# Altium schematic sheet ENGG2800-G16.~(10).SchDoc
size A3
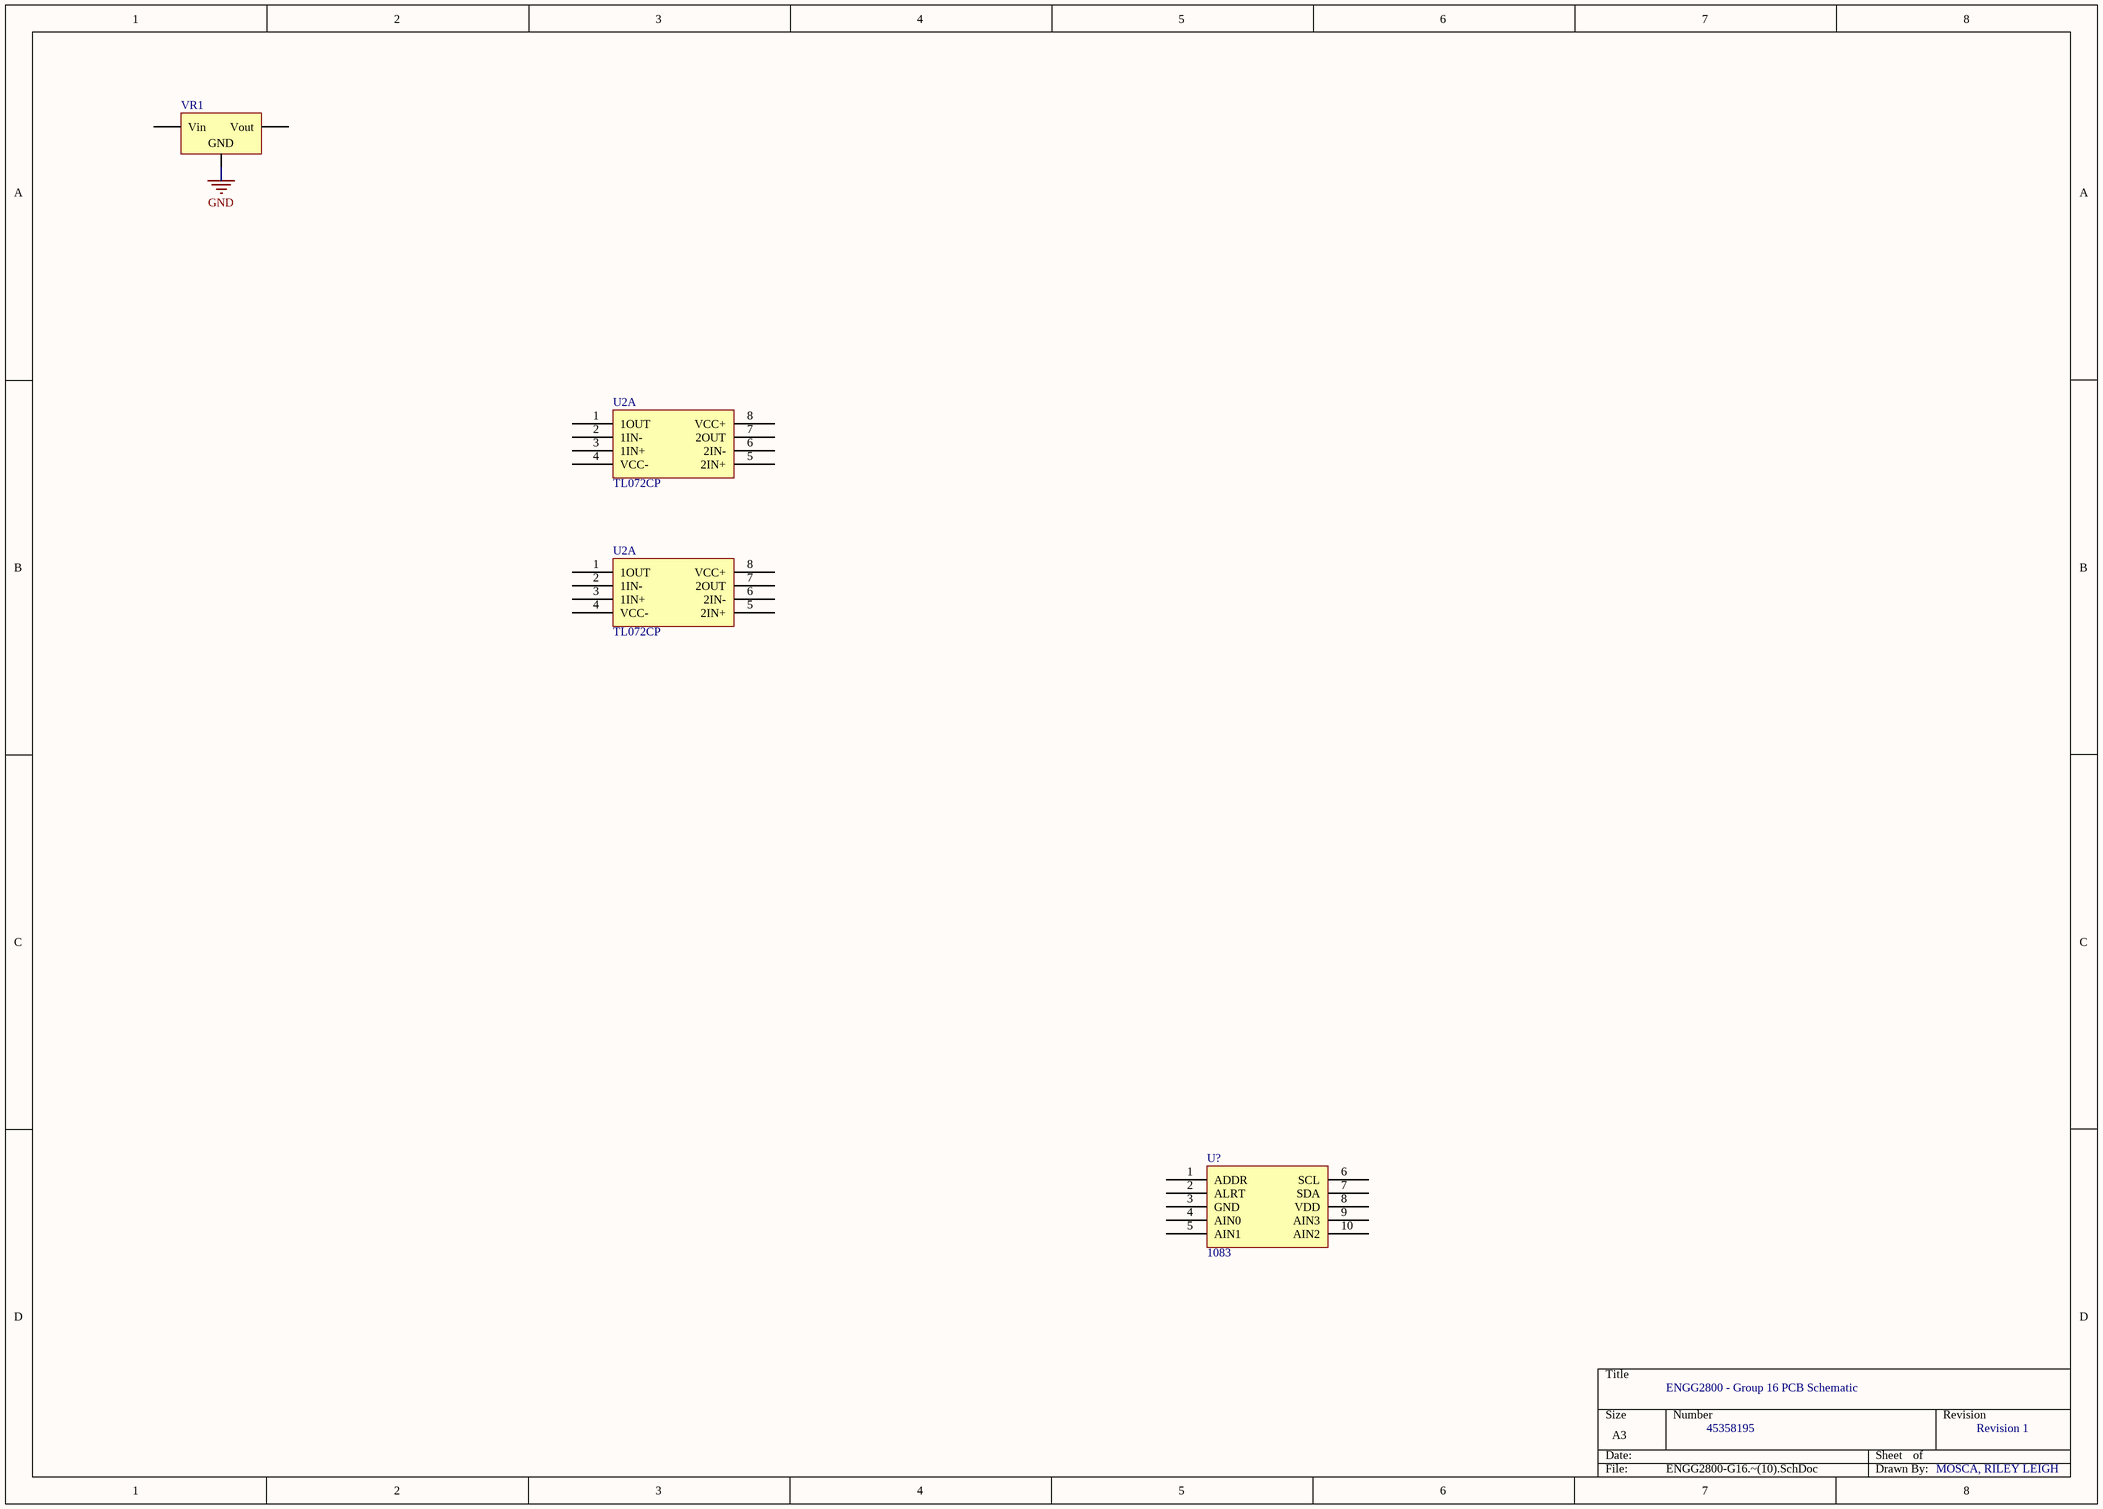
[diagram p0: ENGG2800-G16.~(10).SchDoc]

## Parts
(Parts that share a designator on the sheet are numbered #1, #2 ... from top to bottom, then left to right.)
U2#1  TL072CP  (part A of 4)
U2#2  TL072CP  (part A of 4)
U?  1083
VR1  Volt Reg  [D2PAK_N]  (value not drawn)

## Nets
GND: VR1.2(GND)

Not connected (* = marked no-connect by the designer): U2#1 1(1OUT) 2(1IN-) 3(1IN+) 4(VCC-) 5(2IN+) 6(2IN-) 7(2OUT) 8(VCC+); U2#2 1(1OUT) 2(1IN-) 3(1IN+) 4(VCC-) 5(2IN+) 6(2IN-) 7(2OUT) 8(VCC+); U? 1(ADDR) 2(ALRT) 3(GND) 4(AIN0) 5(AIN1) 6(SCL) 7(SDA) 8(VDD) 9(AIN3) 10(AIN2); VR1 1(Vin) 3(Vout)

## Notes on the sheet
- ENGG2800 - Group 16 PCB Schematic
- 45358195
- Revision 1
- MOSCA, RILEY LEIGH

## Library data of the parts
U2#1 U2#2 = TL072CP: IC, OP AMP, DUAL JFET, DIP8; Bandwidth:3MHz; No. of Amplifiers:2; Slew Rate:13V/ s; Supply Voltage Range:7V to 36V; Amplifier Case Style:DIP; No. of Pins:8; Operating Temperature Min:0 C; Operating Temperature Max:70 C; ;RoHS Compliant: Yes; Manufacturer: Texas Instruments; Bandwidth: 3MHz; Number of Channels: 2; Voltage Gain: 106.02dB; Nominal Supply Current: 5mA; Max Supply Voltage: 18V; Min Dual Supply Voltage: 3.5V; Dual Supply Voltage: 9V; Common Mode Rejection Ratio: 70dB; Slew Rate: 13V/µs; Max I/O Voltage: 10mV; Input Bias Current: 200pA; Input Offset Voltage (Vos): 3mV; Operating Supply Current: 1.4mA
U? = 1083: EVAL BOARD ADS1115 16-BIT ADC; Manufacturer: Adafruit Industries; Number of Bits: 12; Evaluation Kit: Yes; Number of A/D Converters: 1; Sampling Rate: 3300S/s; Interface: I2C,Serial
VR1 = Volt Reg: Voltage Regulator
